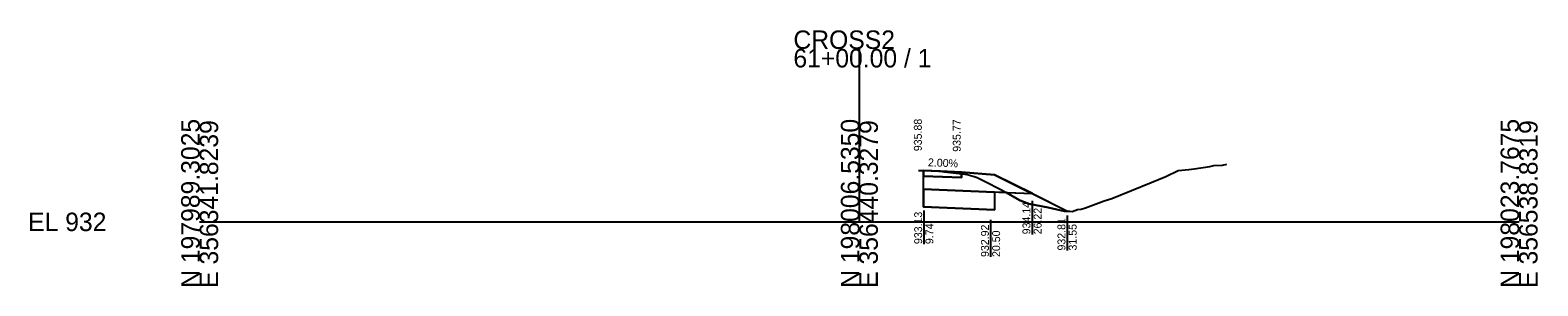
# Model space of a CAD drawing. Extents: x -26 to 203, y -10 to 14021.
# Drawn here: x -25.7 to 202.8, y 1990.3 to 2029 of the extents above; entities that cross this region are included whole.
import ezdxf

# ---------------------------------------------------------------- set-up
doc = ezdxf.new("R2010")
doc.units = 0
for name, color, linetype in [('Default', 7, 'Continuous'), ('P_E_XS_Ground', 7, 'Continuous'), ('P_XS', 7, 'Continuous'), ('P_XS_EAR_CommonGrnd', 7, 'Continuous'), ('P_XS_Lane', 7, 'Continuous'), ('P_XS_Rock', 7, 'Continuous')]:
    doc.layers.add(name, color=color, linetype=linetype)

msp = doc.modelspace()

# ---------------------------------------------------------------- linework, layer by layer
at = {"layer": 'Default'}
for p, q in [((100, 2000), (100, 2026.2)), ((0, 2000), (100, 2000)), ((100, 2000), (200, 2000))]:
    msp.add_line(p, q, dxfattribs=at)
at = {"layer": 'P_E_XS_Ground'}
for p, q in [((108.96, 2007.79), (109.81, 2007.77)), ((109.81, 2007.77), (111.82, 2007.72)), ((111.82, 2007.72), (112.91, 2007.6)), ((112.91, 2007.6), (115.58, 2007.3)), ((115.58, 2007.3), (116.35, 2007.17)), ((116.35, 2007.17), (117.41, 2006.88)), ((117.41, 2006.88), (117.86, 2006.72)), ((117.86, 2006.72), (119.08, 2006.14)), ((144.21, 2005.94), (146.47, 2006.89)), ((146.47, 2006.89), (148.34, 2007.78)), ((148.34, 2007.78), (149.92, 2007.92)), ((149.92, 2007.92), (150.77, 2008.05)), ((150.77, 2008.05), (153.1, 2008.41)), ((153.1, 2008.41), (153.71, 2008.55)), ((153.71, 2008.55), (155.02, 2008.6)), ((155.02, 2008.6), (155.7, 2008.73)), ((119.08, 2006.14), (121.44, 2004.9)), ((121.44, 2004.9), (124.35, 2003.24)), ((138.27, 2003.52), (144.21, 2005.94)), ((124.35, 2003.24), (125.68, 2002.74)), ((125.68, 2002.74), (128.63, 2002.19)), ((128.63, 2002.19), (129.27, 2002.01)), ((129.27, 2002.01), (131.03, 2001.6)), ((133.62, 2001.94), (134.26, 2002.11)), ((134.26, 2002.11), (137.12, 2003.21)), ((137.12, 2003.21), (138.27, 2003.52)), ((131.03, 2001.6), (131.9, 2001.62)), ((131.9, 2001.62), (132.25, 2001.57)), ((132.25, 2001.57), (133.08, 2001.86)), ((133.08, 2001.86), (133.62, 2001.94))]:
    msp.add_line(p, q, dxfattribs=at)
at = {"layer": 'P_XS'}
for p, q in [((109.74, 2007.77), (109.74, 2006.93)), ((109.74, 2006.93), (115.5, 2006.7)), ((109.74, 2004.93), (109.74, 2006.93)), ((115.5, 2007.54), (115.5, 2006.7)), ((109.74, 2004.93), (126.22, 2004.28)), ((109.74, 2004.93), (109.74, 2002.27)), ((120.5, 2004.5), (120.5, 2001.84)), ((109.74, 2002.27), (120.5, 2001.84))]:
    msp.add_line(p, q, dxfattribs=at)
at = {"layer": 'P_XS_EAR_CommonGrnd'}
for points in [[(109.81, 2007.77), (111.82, 2007.72), (112.31, 2007.67), (109.74, 2007.77)], [(112.91, 2007.6), (115.5, 2007.31), (115.5, 2006.7), (109.74, 2006.93), (109.74, 2007.77), (112.31, 2007.67)], [(109.74, 2004.93), (109.74, 2006.93), (115.5, 2006.7), (115.5, 2007.31), (115.58, 2007.3), (116.35, 2007.17), (117.41, 2006.88), (117.86, 2006.72), (119.08, 2006.14), (121.44, 2004.9), (122.26, 2004.43), (120.5, 2004.5)], [(112.91, 2007.6), (115.5, 2007.31), (115.5, 2007.54), (112.31, 2007.67)], [(117.41, 2006.88), (117.86, 2006.72), (119.08, 2006.14), (121.44, 2004.9), (122.26, 2004.43), (126.22, 2004.28), (120.5, 2007.14), (115.5, 2007.54), (115.5, 2007.31), (115.58, 2007.3), (116.35, 2007.17)], [(120.5, 2004.5), (120.5, 2001.84), (109.74, 2002.27), (109.74, 2004.93)], [(122.26, 2004.43), (126.22, 2004.28), (131.55, 2001.61), (131.03, 2001.6), (129.27, 2002.01), (128.63, 2002.19), (125.68, 2002.74), (124.35, 2003.24)]]:
    msp.add_lwpolyline(points, close=True, dxfattribs=at)
at = {"layer": 'P_XS_Lane'}
for p, q in [((109.74, 2007.77), (115.5, 2007.54)), ((115.5, 2007.54), (120.5, 2007.14)), ((120.5, 2007.14), (131.55, 2001.61))]:
    msp.add_line(p, q, dxfattribs=at)
at = {"layer": 'P_XS_Rock'}
for p, q in [((126.17, 2003.21), (126.17, 1998.11)), ((109.76, 2001.74), (109.76, 1996.63)), ((119.88, 2000.29), (119.88, 1994.68)), ((131.48, 2000.95), (131.48, 1995.65))]:
    msp.add_line(p, q, dxfattribs=at)

# ---------------------------------------------------------------- texts
at = {"layer": 'Default'}
for s, p in [('CROSS2', (90, 2026.2)), ('61+00.00 / 1', (90, 2023.4)), ('EL 932', (-26, 1998.6))]:
    msp.add_text(s, height=2.8, dxfattribs=at).set_placement(p)
for s, p in [('N 197989.3025', (0, 1990)), ('E 356341.8239', (2.8, 1990)), ('N 198006.5350', (100, 1990)), ('E 356440.3279', (102.8, 1990)), ('N 198023.7675', (200, 1990)), ('E 356538.8319', (202.8, 1990))]:
    msp.add_text(s, height=2.8, rotation=90, dxfattribs=at).set_placement(p)
at = {"layer": 'P_XS_Rock'}
for s, rotation, p in [('935.88', 90, (109.46, 2010.71)), ('935.77', 90, (115.36, 2010.62)), ('2.00%', 357.7094, (110.38, 2008.43)), ('934.14', 90, (125.92, 1998.11)), ('26.22', 90, (127.62, 1998.11)), ('933.13', 90, (109.51, 1996.63)), ('9.74', 90, (111.21, 1996.63)), ('932.81', 90, (131.23, 1995.66)), ('932.92', 90, (119.63, 1994.68)), ('20.50', 90, (121.33, 1994.68)), ('31.55', 90, (132.93, 1995.66))]:
    msp.add_text(s, height=1.2, rotation=rotation, dxfattribs=at).set_placement(p)

doc.saveas('drawing.dxf')
